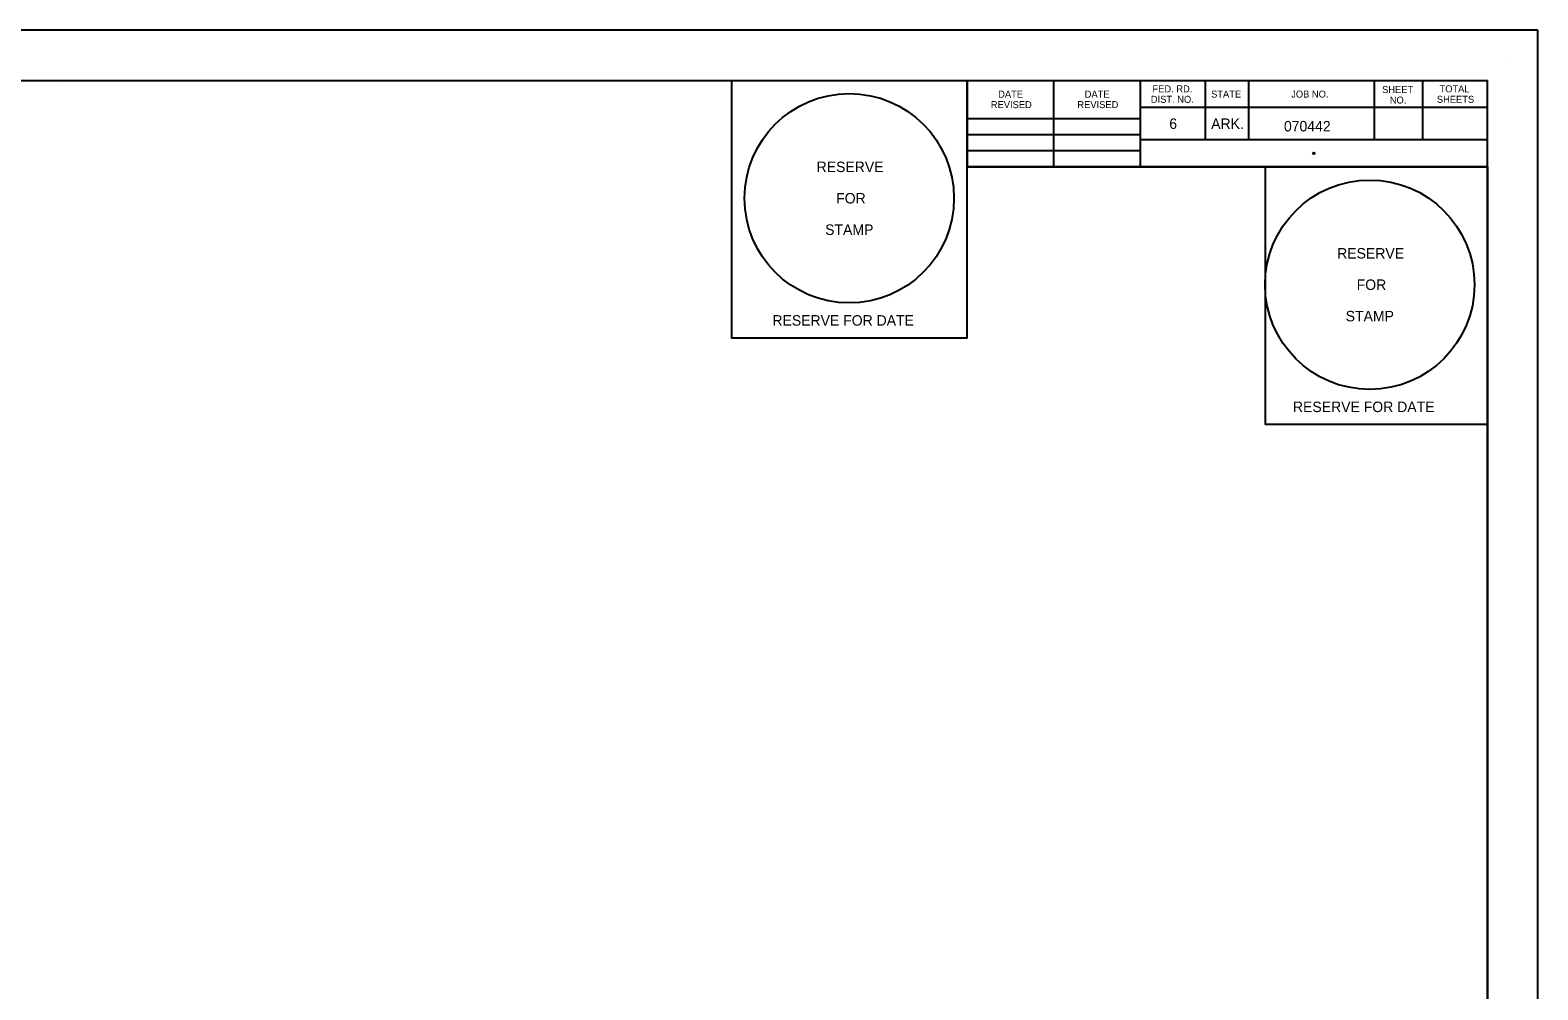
# Model space of a CAD drawing. Extents: x 1448008.9 to 1448042.9, y 2057057.8 to 2057079.8.
# Drawn here: x 1448025.66 to 1448042.95, y 2057068.82 to 2057079.82 of the extents above; entities that cross this region are included whole.
import ezdxf

# ---------------------------------------------------------------- set-up
doc = ezdxf.new("R2010")
doc.units = 0
for name, color, linetype in [('1', 7, 'Continuous'), ('G-ANNO-TEXT', 7, 'Continuous'), ('G-Border-Sheet', 7, 'Continuous'), ('G-No Plot-Anchor', 7, 'Continuous'), ('G-No Plot-Border-1', 7, 'Continuous'), ('G-No Plot-Border-2', 7, 'Continuous'), ('G-No Plot-Stamp-1', 7, 'Continuous'), ('G-No Plot-Stamp-2', 7, 'Continuous'), ('G-Table-Major', 7, 'Continuous'), ('G-Table-Minor', 7, 'Continuous')]:
    doc.layers.add(name, color=color, linetype=linetype)

msp = doc.modelspace()

# ---------------------------------------------------------------- linework, layer by layer
at = {"layer": '1'}
msp.add_lwpolyline([(1448042.945, 2057079.818), (1448008.945, 2057079.818), (1448008.945, 2057057.818), (1448042.945, 2057057.818)], close=True, dxfattribs=at)
at = {"layer": 'G-ANNO-TEXT'}
msp.add_line((1448042.588, 2057079.472), (1448042.588, 2057079.472), dxfattribs=at)
at = {"layer": 'G-Border-Sheet'}
for p in [(1448010.461, 2057079.241), (1448042.369, 2057058.395)]:
    msp.add_line(p, (1448042.369, 2057079.241), dxfattribs=at)
at = {"layer": 'G-No Plot-Anchor'}
msp.add_circle((1448040.378, 2057078.406), 0.01, dxfattribs=at)
at = {"layer": 'G-No Plot-Border-1'}
msp.add_lwpolyline([(1448010.461, 2057058.395), (1448010.461, 2057079.241), (1448036.402, 2057079.241), (1448036.402, 2057078.25), (1448039.819, 2057078.25), (1448039.819, 2057075.3), (1448042.369, 2057075.3), (1448042.369, 2057058.395)], close=True, dxfattribs=at)
at = {"layer": 'G-No Plot-Border-2'}
msp.add_lwpolyline([(1448010.461, 2057058.395), (1448010.461, 2057079.241), (1448033.702, 2057079.241), (1448033.702, 2057076.291), (1448036.402, 2057076.291), (1448036.402, 2057078.25), (1448038.387, 2057078.25), (1448042.369, 2057078.25), (1448042.369, 2057058.395)], close=True, dxfattribs=at)
at = {"layer": 'G-No Plot-Stamp-1'}
msp.add_circle((1448041.019, 2057076.9), 1.2, dxfattribs=at)
at = {"layer": 'G-No Plot-Stamp-2'}
msp.add_circle((1448035.052, 2057077.891), 1.2, dxfattribs=at)
at = {"layer": 'G-Table-Major'}
for p, q in [((1448036.402, 2057078.251), (1448036.402, 2057079.241)), ((1448038.387, 2057079.241), (1448038.387, 2057078.25)), ((1448036.402, 2057078.807), (1448038.387, 2057078.807)), ((1448042.369, 2057078.25), (1448036.402, 2057078.25))]:
    msp.add_line(p, q, dxfattribs=at)
at = {"layer": 'G-Table-Minor'}
for p, q in [((1448037.397, 2057078.251), (1448037.397, 2057079.241)), ((1448039.131, 2057079.241), (1448039.131, 2057078.561)), ((1448039.628, 2057079.241), (1448039.628, 2057078.561)), ((1448041.069, 2057079.241), (1448041.069, 2057078.561)), ((1448041.625, 2057079.241), (1448041.625, 2057078.561)), ((1448026.003, 2057079.215), (1448026.003, 2057079.215)), ((1448026.003, 2057079.215), (1448026.003, 2057079.215)), ((1448042.369, 2057078.93), (1448038.387, 2057078.93)), ((1448042.369, 2057078.949), (1448042.369, 2057078.949)), ((1448036.402, 2057078.62), (1448038.387, 2057078.62)), ((1448042.369, 2057078.561), (1448038.387, 2057078.561)), ((1448036.402, 2057078.437), (1448038.387, 2057078.437))]:
    msp.add_line(p, q, dxfattribs=at)

# ---------------------------------------------------------------- texts
at = {"layer": 'G-ANNO-TEXT'}
for s, height, p in [('DATE', 0.08, (1448036.759, 2057079.044)), ('DATE', 0.08, (1448037.751, 2057079.044)), ('DIST. NO.', 0.08, (1448038.509, 2057078.985)), ('FED. RD.', 0.08, (1448038.528, 2057079.105)), ('STATE', 0.08, (1448039.2, 2057079.045)), ('JOB NO.', 0.08, (1448040.118, 2057079.045)), ('SHEET', 0.08, (1448041.16, 2057079.097)), ('NO.', 0.08, (1448041.248, 2057078.977)), ('SHEETS', 0.08, (1448041.788, 2057078.985)), ('TOTAL', 0.08, (1448041.818, 2057079.105)), ('REVISED', 0.08, (1448036.675, 2057078.924)), ('REVISED', 0.08, (1448037.667, 2057078.924)), ('6', 0.12, (1448038.721, 2057078.686)), ('ARK.', 0.12, (1448039.201, 2057078.686)), ('070442', 0.12, (1448040.035, 2057078.657))]:
    msp.add_text(s, height=height, dxfattribs=at).set_placement(p)
at = {"layer": 'G-No Plot-Stamp-1'}
for s, p in [('RESERVE', (1448040.645, 2057077.2)), ('FOR ', (1448040.869, 2057076.84)), ('STAMP', (1448040.743, 2057076.48)), ('RESERVE FOR DATE', (1448040.138, 2057075.44))]:
    msp.add_text(s, height=0.12, dxfattribs=at).set_placement(p)
at = {"layer": 'G-No Plot-Stamp-2'}
for s, p in [('RESERVE', (1448034.678, 2057078.191)), ('FOR ', (1448034.902, 2057077.831)), ('STAMP', (1448034.776, 2057077.471)), ('RESERVE FOR DATE', (1448034.171, 2057076.431))]:
    msp.add_text(s, height=0.12, dxfattribs=at).set_placement(p)

doc.saveas('drawing.dxf')
